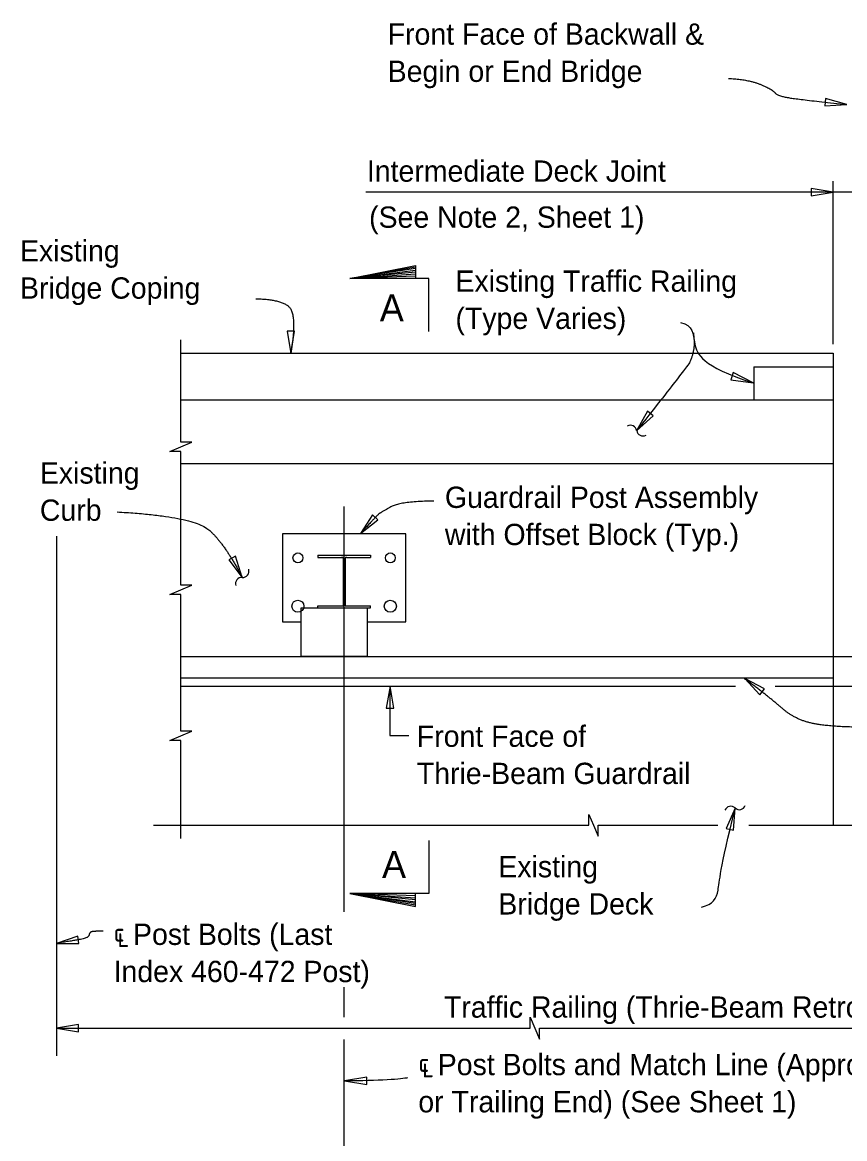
# Model space of a CAD drawing. Extents: x 21587 to 21656.3, y 56114 to 56157.2.
# Drawn here: x 21605.81 to 21613.6, y 56142.29 to 56152.85 of the extents above; entities that cross this region are included whole.
import ezdxf

# ---------------------------------------------------------------- set-up
doc = ezdxf.new("R2010")
doc.units = 0
for name, color, linetype in [('AdhocPoint_dp', 7, 'Continuous'), ('Border', 7, 'Continuous'), ('PlotBorder_dp', 7, 'Continuous'), ('SheetBorder_dp', 7, 'Continuous'), ('TextMisc', 7, 'Continuous')]:
    doc.layers.add(name, color=color, linetype=linetype)

msp = doc.modelspace()

# ---------------------------------------------------------------- linework, layer by layer
at = {"layer": 'AdhocPoint_dp'}
for p, q in [((21613.488, 56149.72), (21607.312, 56149.72)), ((21613.488, 56149.722), (21613.488, 56145.254)), ((21612.738, 56149.595), (21613.488, 56149.595)), ((21607.312, 56149.282), (21613.488, 56149.282)), ((21607.312, 56148.678), (21613.488, 56148.678)), ((21607.312, 56146.648), (21613.488, 56146.648))]:
    msp.add_line(p, q, dxfattribs=at)
msp.add_lwpolyline([(21612.738, 56149.595), (21612.738, 56149.282)], dxfattribs=at)
at = {"layer": 'Border'}
for p, q in [((21608.608, 56147.811), (21609.108, 56147.811)), ((21608.608, 56147.811), (21608.608, 56147.79)), ((21608.608, 56147.79), (21608.837, 56147.79)), ((21608.848, 56147.78), (21608.848, 56147.332)), ((21608.868, 56147.78), (21608.868, 56147.332)), ((21608.879, 56147.79), (21609.108, 56147.79)), ((21609.108, 56147.811), (21609.108, 56147.79)), ((21608.608, 56147.332), (21608.848, 56147.332)), ((21608.608, 56147.311), (21608.608, 56147.332)), ((21608.608, 56147.311), (21609.108, 56147.311)), ((21608.868, 56147.332), (21609.108, 56147.332)), ((21609.108, 56147.311), (21609.108, 56147.332)), ((21607.312, 56146.851), (21619.379, 56146.851)), ((21607.312, 56146.57), (21612.565, 56146.57)), ((21612.941, 56146.57), (21619.379, 56146.57))]:
    msp.add_line(p, q, dxfattribs=at)
msp.add_lwpolyline([(21609.077, 56147.181), (21609.441, 56147.181), (21609.441, 56148.014), (21608.275, 56148.014), (21608.275, 56147.181), (21608.452, 56147.181)], dxfattribs=at)
for centre, radius in [((21608.42, 56147.785), 0.0469), ((21609.295, 56147.785), 0.0469), ((21608.42, 56147.327), 0.0573), ((21609.295, 56147.327), 0.0573)]:
    msp.add_circle(centre, radius, dxfattribs=at)
for centre, start, end in [((21608.837, 56147.78), 0, 90), ((21608.879, 56147.78), 90, 180)]:
    msp.add_arc(centre, 0.0104, start, end, dxfattribs=at)
at = {"layer": 'PlotBorder_dp'}
for p, q in [((21613.488, 56149.808), (21613.488, 56151.352)), ((21613.996, 56151.248), (21609.063, 56151.248)), ((21608.91, 56150.429), (21609.535, 56150.539)), ((21609.535, 56150.526), (21608.91, 56150.429)), ((21608.91, 56150.429), (21609.535, 56150.509)), ((21609.535, 56150.491), (21608.91, 56150.429)), ((21608.91, 56150.429), (21609.535, 56150.473)), ((21609.535, 56150.453), (21608.91, 56150.429)), ((21608.858, 56144.434), (21608.858, 56148.27)), ((21609.535, 56144.586), (21608.91, 56144.609)), ((21608.91, 56144.609), (21609.535, 56144.566)), ((21609.535, 56144.547), (21608.91, 56144.609)), ((21608.91, 56144.609), (21609.535, 56144.529)), ((21609.535, 56144.512), (21608.91, 56144.609)), ((21608.91, 56144.609), (21609.535, 56144.499)), ((21608.858, 56143.438), (21608.858, 56143.72)), ((21608.858, 56135.158), (21608.858, 56143.226))]:
    msp.add_line(p, q, dxfattribs=at)
for points in [[(21613.62, 56152.078), (21613.416, 56152.134), (21613.409, 56152.064)], [(21613.488, 56151.248), (21613.28, 56151.283), (21613.28, 56151.212)], [(21608.352, 56149.721), (21608.388, 56149.93), (21608.317, 56149.93)], [(21612.73, 56149.441), (21612.543, 56149.539), (21612.521, 56149.472)], [(21611.628, 56148.989), (21611.785, 56149.131), (21611.73, 56149.175)], [(21609.011, 56148.015), (21609.178, 56148.144), (21609.126, 56148.192)], [(21607.893, 56147.6), (21607.828, 56147.801), (21607.765, 56147.768)], [(21609.292, 56146.57), (21609.257, 56146.361), (21609.327, 56146.361)], [(21612.651, 56146.642), (21612.796, 56146.489), (21612.839, 56146.546)], [(21612.562, 56145.417), (21612.477, 56145.224), (21612.546, 56145.207)], [(21606.135, 56144.136), (21606.346, 56144.133), (21606.335, 56144.203)], [(21606.135, 56143.332), (21606.343, 56143.297), (21606.343, 56143.368)], [(21608.862, 56142.834), (21609.071, 56142.799), (21609.071, 56142.869)]]:
    msp.add_lwpolyline(points, close=True, dxfattribs=at)
for points in [[(21609.66, 56149.929), (21609.66, 56150.429), (21608.91, 56150.429), (21609.535, 56150.554), (21609.535, 56150.429)], [(21607.312, 56148.322), (21607.312, 56148.791), (21607.208, 56148.791), (21607.312, 56148.836), (21607.415, 56148.881), (21607.312, 56148.881), (21607.312, 56149.85)], [(21607.312, 56146.575), (21607.312, 56147.438), (21607.208, 56147.438), (21607.312, 56147.483), (21607.415, 56147.528), (21607.312, 56147.528), (21607.312, 56148.322)], [(21607.312, 56145.128), (21607.312, 56146.056), (21607.208, 56146.056), (21607.312, 56146.101), (21607.415, 56146.146), (21607.312, 56146.146), (21607.312, 56147.019)], [(21607.053, 56145.254), (21611.175, 56145.254), (21611.175, 56145.357), (21611.22, 56145.254), (21611.265, 56145.15), (21611.265, 56145.254), (21612.396, 56145.254)], [(21613.496, 56145.254), (21617.776, 56145.254), (21617.776, 56145.357), (21617.821, 56145.254), (21617.866, 56145.15), (21617.866, 56145.254), (21620.131, 56145.254)], [(21612.689, 56145.254), (21613.496, 56145.254)], [(21609.66, 56145.109), (21609.66, 56144.609), (21608.91, 56144.609), (21609.535, 56144.484), (21609.535, 56144.609)], [(21606.135, 56143.332), (21610.618, 56143.332), (21610.618, 56143.436), (21610.663, 56143.332), (21610.708, 56143.229), (21610.708, 56143.332), (21626.014, 56143.332)]]:
    msp.add_lwpolyline(points, dxfattribs=at)
for centre, start, end in [((21611.569, 56148.981), 8.6098, 120.3371), ((21611.687, 56148.999), 188.6098, 300.3371), ((21607.897, 56147.659), 265.5858, 17.313), ((21607.888, 56147.54), 85.5858, 197.313), ((21612.52, 56145.374), 47.1839, 158.9112), ((21612.601, 56145.461), 227.1839, 338.9112)]:
    msp.add_arc(centre, 0.0596, start, end, dxfattribs=at)
for points, degree in [([(21612.498, 56152.323), (21612.683, 56152.316), (21612.921, 56152.217), (21612.954, 56152.158), (21613.224, 56152.118), (21613.62, 56152.078)], 2), ([(21608.02, 56150.237), (21608.232, 56150.237), (21608.418, 56150.106), (21608.352, 56149.721)], 2), ([(21612.043, 56150.014), (21612.164, 56149.987), (21612.156, 56149.83), (21612.239, 56149.6), (21612.73, 56149.441)], 3), ([(21612.165, 56149.915), (21612.179, 56149.807), (21612.151, 56149.678), (21612.108, 56149.595), (21611.628, 56148.989)], 2), ([(21609.708, 56148.323), (21609.39, 56148.32), (21609.205, 56148.213), (21609.177, 56148.196), (21609.011, 56148.015)], 2), ([(21606.708, 56148.22), (21607.434, 56148.18), (21607.731, 56147.911), (21607.893, 56147.6)], 2), ([(21609.47, 56146.101), (21609.292, 56146.101), (21609.292, 56146.101), (21609.292, 56146.411), (21609.292, 56146.57)], 2), ([(21613.905, 56146.18), (21613.496, 56146.18), (21613.139, 56146.246), (21612.888, 56146.464), (21612.651, 56146.642)], 2), ([(21612.241, 56144.48), (21612.355, 56144.502), (21612.413, 56144.619), (21612.413, 56144.821), (21612.562, 56145.417)], 3), ([(21606.577, 56144.252), (21606.511, 56144.251), (21606.447, 56144.245), (21606.438, 56144.188), (21606.312, 56144.164), (21606.135, 56144.136)], 2), ([(21609.459, 56142.862), (21609.437, 56142.858), (21609.298, 56142.841), (21609.025, 56142.834), (21608.862, 56142.834)], 3)]:
    msp.add_open_spline(points, degree=degree, dxfattribs=at)
at = {"layer": 'TextMisc'}
msp.add_line((21606.135, 56147.992), (21606.135, 56143.07), dxfattribs=at)
msp.add_lwpolyline([(21609.077, 56147.311), (21609.077, 56146.853), (21608.452, 56146.853), (21608.452, 56147.311)], close=True, dxfattribs=at)

# ---------------------------------------------------------------- texts
at = {"layer": 'PlotBorder_dp'}
for s, p in [('Front Face of Backwall &', (21609.27, 56152.643)), ('Begin or End Bridge', (21609.27, 56152.291)), ('Existing ', (21605.788, 56150.591)), ('Existing Traffic Railing', (21609.912, 56150.304)), ('Bridge Coping ', (21605.788, 56150.239)), ('(Type Varies)', (21609.912, 56149.952)), ('Existing ', (21605.976, 56148.488)), ('Guardrail Post Assembly ', (21609.812, 56148.258)), ('Curb', (21605.976, 56148.136)), ('with Offset Block (Typ.)', (21609.812, 56147.906)), ('Front Face of ', (21609.546, 56145.996)), ('Thrie-Beam Guardrail', (21609.546, 56145.644)), ('Existing ', (21610.318, 56144.761)), ('Bridge Deck', (21610.318, 56144.409)), ('℄ Post Bolts (Last', (21606.674, 56144.121)), ('Index 460-472 Post)', (21606.674, 56143.769)), ('℄ Post Bolts and Match Line (Approach  ', (21609.56, 56142.888)), ('or Trailing End) (See Sheet 1)', (21609.56, 56142.536))]:
    msp.add_text(s, height=0.2016, dxfattribs=at).set_placement(p)
at = {"layer": 'SheetBorder_dp'}
for s, height, p in [('Intermediate Deck Joint', 0.2016, (21609.073, 56151.346)), ('(See Note 2, Sheet 1)', 0.2016, (21609.094, 56150.91)), ('A', 0.256, (21609.195, 56150.023)), ('A', 0.256, (21609.216, 56144.754)), ('Traffic Railing (Thrie-Beam Retrofit) Limits of Payment', 0.2016, (21609.803, 56143.432))]:
    msp.add_text(s, height=height, dxfattribs=at).set_placement(p)

doc.saveas('drawing.dxf')
